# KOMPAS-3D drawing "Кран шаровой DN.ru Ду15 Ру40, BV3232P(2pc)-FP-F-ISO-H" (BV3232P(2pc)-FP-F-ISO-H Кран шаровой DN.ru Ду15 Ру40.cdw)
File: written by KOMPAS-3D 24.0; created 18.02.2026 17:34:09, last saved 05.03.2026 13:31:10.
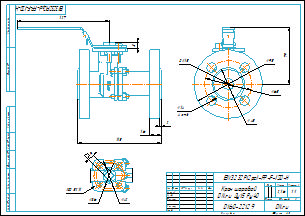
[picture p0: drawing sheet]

Document properties: Автор: R2D2; Форматы листов документа: A3; Полное имя файла: BV3232P(2pc)-FP-F-ISO-H Кран шаровой DN.ru Ду15 Ру40.m3d; Масса: 2.16; Наименование: Кран шаровой DN.ru Ду15 Ру40; Количество листов документа: 1; Примечание: D160-22129

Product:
- Part/product: Кран шаровой DN.ru Ду15 Ру40  | designation BV3232P(2pc)-FP-F-ISO-H
    Масса: 2.16
    Раздел спецификации: Прочие изделия
    Форматы листов документа: A3
    Примечание: D160-22129

Views: Проекционный вид 2, Проекционный вид 3
Referenced files in E:\Работа\Зайцев\BV3232P(2pc)-FP-F-ISO-H Кран шаровой DN.ru Ду15-300 Ру16-40\DN15\: BV3232P(2pc)-FP-F-ISO-H Кран шаровой DN.ru Ду15 Ру40.m3d
Referenced files in E:\Работа\Зайцев\Для компаса\: чертеж DN.ru А3.cdt
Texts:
  BV3232P(2pc)-FP-F-ISO-H
  ISO 5211
  чертеж DN.ru А3.cdt
  Кран шаровой
  DN.ru Ду15 Ру40
  Кран шаровой DN.ru Ду15 Ру40
  BV3232P(2pc)-FP-F-ISO-H Кран шаровой DN.ru Ду15 Ру40
Dimensions and other numbers on the sheet: 0; 3; 4; 15; 65; 95; 14; 4 отв.; 79; 45; 42; 36; 9; 1:1; 1; 2; 2,16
